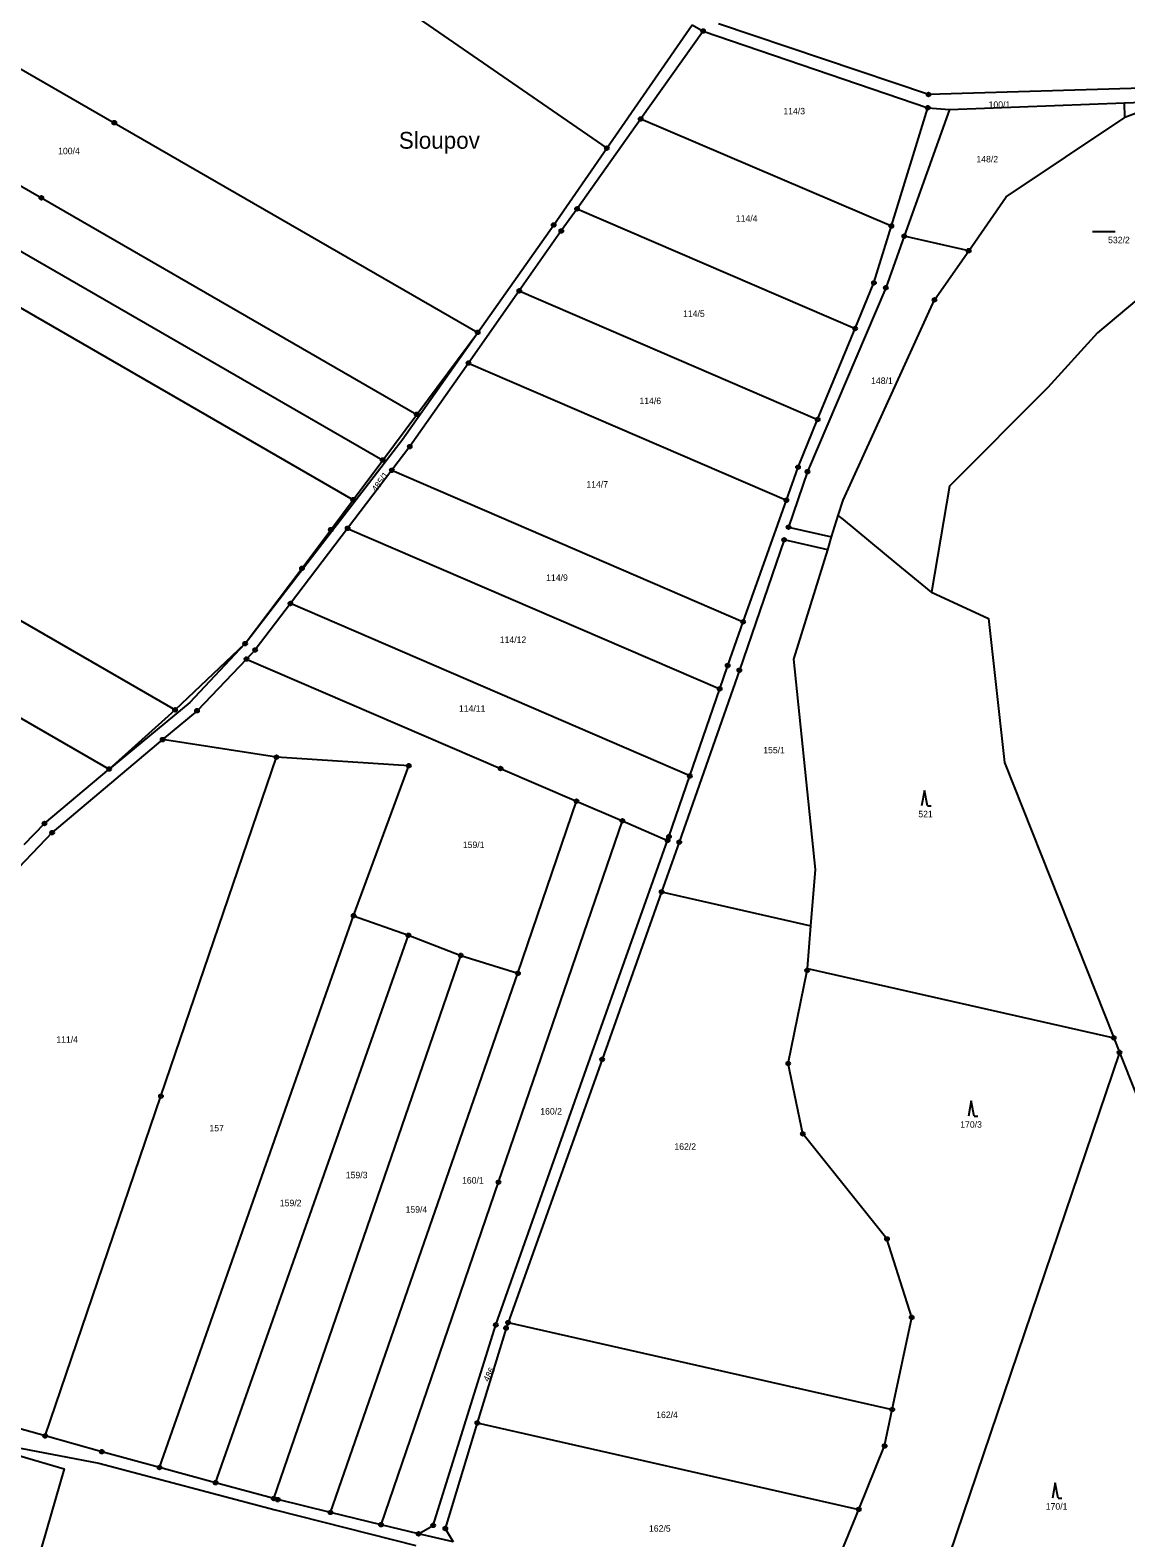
# Model space of a CAD drawing. Extents: x -758582 to -751794, y -998770 to -994350.
# Drawn here: x -756217.6 to -755930.2, y -996868.5 to -996472.9 of the extents above; entities that cross this region are included whole.
import ezdxf

# ---------------------------------------------------------------- set-up
doc = ezdxf.new("R2010")
doc.units = 0
for name, color, linetype in [('Hranice parcel', 7, 'Continuous'), ('Parcelní čísla', 7, 'Continuous'), ('Pop  PČ popisy', 7, 'Continuous'), ('Vnitřní kresba', 7, 'Continuous'), ('Značky bodu BP', 7, 'Continuous'), ('Značky kultur', 7, 'Continuous')]:
    doc.layers.add(name, color=color, linetype=linetype)

msp = doc.modelspace()

# ---------------------------------------------------------------- linework, layer by layer
at = {"layer": 'Hranice parcel'}
for p, q in [((-756066.33, -996503.89), (-756043.93, -996471.51)), ((-756043.93, -996471.51), (-756041.08, -996473.16)), ((-756041.08, -996473.16), (-756057.45, -996496.24)), ((-756041.08, -996473.16), (-755982.13, -996493.28)), ((-755976.39, -996493.79), (-755930.55, -996492.03)), ((-755930.4, -996495.89), (-755930.55, -996492.03)), ((-756057.45, -996496.24), (-756074.15, -996519.8)), ((-756057.45, -996496.24), (-755991.67, -996524.32)), ((-755991.67, -996524.32), (-755982.13, -996493.28)), ((-755976.39, -996493.79), (-755988.3, -996526.99)), ((-755982.13, -996493.28), (-755976.39, -996493.79)), ((-756074.15, -996519.8), (-756001.19, -996551.22)), ((-755971.4, -996530.81), (-755988.3, -996526.99)), ((-756089.3, -996541.32), (-756102.63, -996560.29)), ((-756089.3, -996541.32), (-756011.02, -996575.11)), ((-756011.02, -996575.11), (-756001.19, -996551.22)), ((-756116.22, -996573.74), (-756100.21, -996552.23)), ((-756102.63, -996560.29), (-756019.24, -996596.29)), ((-756125.14, -996585.72), (-756116.22, -996573.74)), ((-756132.9, -996596.13), (-756125.14, -996585.72)), ((-756122.74, -996588.41), (-756134.34, -996603.65)), ((-756122.74, -996588.41), (-756030.56, -996628.2)), ((-756030.56, -996628.2), (-756019.24, -996596.29)), ((-756007.36, -996605.92), (-756005.61, -996600.26)), ((-756134.34, -996603.65), (-756149.36, -996623.39)), ((-756134.34, -996603.65), (-756036.73, -996645.78)), ((-756008.39, -996609.26), (-756007.36, -996605.92)), ((-756044.57, -996668.63), (-756149.36, -996623.39)), ((-756044.57, -996668.63), (-756036.73, -996645.78)), ((-756196.89, -996666.8), (-756179.61, -996651.27)), ((-756153, -996663.68), (-756182.87, -996659.09)), ((-756089.66, -996720.4), (-756074.29, -996675.23)), ((-756074.29, -996675.23), (-756062.26, -996680.41)), ((-756062.26, -996680.41), (-756050.38, -996685.53)), ((-756051.97, -996699.06), (-756012.79, -996707.93)), ((-756183.71, -996850.06), (-756132.77, -996705.3)), ((-756132.77, -996705.3), (-756118.4, -996710.43)), ((-756013.73, -996719.12), (-756012.79, -996707.93)), ((-756168.97, -996854.06), (-756118.4, -996710.43)), ((-756118.4, -996710.43), (-756104.62, -996715.71)), ((-756153.73, -996858.21), (-756104.62, -996715.71)), ((-756104.62, -996715.71), (-756089.66, -996720.4)), ((-756138.83, -996861.86), (-756089.66, -996720.4)), ((-756013.73, -996719.12), (-755933.35, -996737.32)), ((-755933.35, -996737.32), (-755931.83, -996741.15)), ((-756092.26, -996812.05), (-755991.44, -996834.87)), ((-756213.7, -996841.79), (-756229.38, -996837.41)), ((-756100.32, -996838.38), (-756000.21, -996861.05)), ((-756168.97, -996854.06), (-756183.71, -996850.06)), ((-756153.73, -996858.21), (-756168.97, -996854.06)), ((-756125.58, -996865.08), (-756138.83, -996861.86)), ((-756115.72, -996867.47), (-756125.58, -996865.08)), ((-756106.65, -996869.59), (-756115.72, -996867.47))]:
    msp.add_line(p, q, dxfattribs=at)
for points in [[(-756223.89, -996395.2), (-756148.16, -996447.44), (-756066.33, -996503.89)], [(-756289.97, -996442.74), (-756195.56, -996497.21), (-756100.21, -996552.23)], [(-756311.7, -996460.95), (-756214.69, -996516.92), (-756116.22, -996573.74)], [(-756323.8, -996471.09), (-756224.19, -996528.57), (-756125.14, -996585.72)], [(-755738.63, -996514.47), (-755788.99, -996494.25), (-755817.97, -996485.34), (-755849.85, -996483.58), (-755913.99, -996487.85), (-755981.92, -996489.8), (-756037.02, -996471.24)], [(-756334.9, -996479.57), (-756234.43, -996537.55), (-756132.9, -996596.13)], [(-755930.55, -996492.03), (-755916.39, -996491.48), (-755851.5, -996487.03), (-755818.69, -996488.48), (-755807.65, -996491.97)], [(-755808.28, -996494.77), (-755818.67, -996491.26), (-755850.72, -996490.71), (-755890.14, -996491.25), (-755898.35, -996497.16), (-755911.43, -996492.83), (-755924.16, -996493.48), (-755930.4, -996495.89)], [(-755971.4, -996530.81), (-755961.54, -996516.68), (-755930.4, -996495.89)], [(-756100.21, -996552.23), (-756080.28, -996524.04), (-756066.33, -996503.89)], [(-756074.15, -996519.8), (-756078.28, -996525.63), (-756089.3, -996541.32)], [(-755815.82, -996528.07), (-755858.93, -996519.76), (-755919.17, -996536.86), (-755937.62, -996552.31), (-755950.67, -996566.72), (-755976.44, -996592.58), (-755981.16, -996620.43)], [(-755988.3, -996526.99), (-755993.15, -996540.51), (-756013.69, -996588.78), (-756018.69, -996603.35), (-756007.36, -996605.92)], [(-756001.19, -996551.22), (-755996.26, -996539.24), (-755991.67, -996524.32)], [(-756389.84, -996529.96), (-756284.41, -996590.79), (-756179.61, -996651.27)], [(-756005.61, -996600.26), (-756004.36, -996596.24), (-755980.38, -996543.69), (-755971.4, -996530.81)], [(-756403, -996547.87), (-756300.36, -996607.1), (-756196.89, -996666.8)], [(-756102.63, -996560.29), (-756118.02, -996582.2), (-756122.74, -996588.41)], [(-756019.24, -996596.29), (-756016.16, -996587.62), (-756011.02, -996575.11)], [(-756179.61, -996651.27), (-756161.24, -996633.9), (-756146.32, -996614.15), (-756138.76, -996604), (-756132.9, -996596.13)], [(-755981.16, -996620.43), (-755990.41, -996612.79), (-756004.25, -996601.37), (-756005.61, -996600.26)], [(-756008.39, -996609.26), (-756019.82, -996606.66), (-756031.57, -996640.89), (-756047.33, -996685.99), (-756051.97, -996699.06)], [(-756012.79, -996707.93), (-756011.56, -996693.13), (-756017.3, -996638.02), (-756008.39, -996609.26)], [(-755981.16, -996620.43), (-755966.24, -996627.28), (-755962.03, -996665.05), (-755933.35, -996737.32)], [(-756149.36, -996623.39), (-756158.6, -996635.55), (-756160.88, -996637.94)], [(-756036.73, -996645.78), (-756034.63, -996639.67), (-756030.56, -996628.2)], [(-756160.88, -996637.94), (-756173.86, -996651.51), (-756182.87, -996659.09)], [(-756160.88, -996637.94), (-756094.21, -996666.65), (-756074.29, -996675.23)], [(-756182.87, -996659.09), (-756211.86, -996683.49), (-756234.83, -996707.54), (-756253.45, -996735.72), (-756269.43, -996768.85), (-756277.38, -996793.04)], [(-756213.7, -996841.79), (-756183.32, -996752.66), (-756153, -996663.68)], [(-756132.77, -996705.3), (-756118.27, -996665.94), (-756153, -996663.68)], [(-756219.23, -996686.58), (-756213.87, -996681.09), (-756196.89, -996666.8)], [(-756050.38, -996685.53), (-756050.04, -996684.56), (-756044.57, -996668.63)], [(-756125.58, -996865.08), (-756094.76, -996775.21), (-756062.26, -996680.41)], [(-756115.72, -996867.47), (-756111.89, -996865.26), (-756095.44, -996812.67), (-756070.18, -996741.19), (-756050.38, -996685.53)], [(-756051.97, -996699.06), (-756067.56, -996742.99), (-756092.26, -996812.05)], [(-755991.44, -996834.87), (-755986.35, -996810.68), (-755992.83, -996790.11), (-756014.92, -996762.53), (-756018.74, -996744.05), (-756013.77, -996719.63), (-756013.73, -996719.12)], [(-755931.83, -996741.15), (-755985.33, -996899.18), (-756004.65, -996895), (-756005.17, -996894.89)], [(-755931.83, -996741.15), (-755910.72, -996794.08), (-755898.01, -996825.36)], [(-756092.26, -996812.05), (-756092.78, -996813.49), (-756100.32, -996838.38)], [(-756000.21, -996861.05), (-755993.45, -996844.42), (-755991.44, -996834.87)], [(-756100.32, -996838.38), (-756108.71, -996866.09), (-756106.65, -996869.59)], [(-756240.4, -996841.13), (-756208.7, -996850.39), (-756227.33, -996914.64), (-756266.64, -996902.35), (-756265.2, -996898.6), (-756260.73, -996899.5), (-756245.41, -996846.34)], [(-756240.4, -996841.13), (-756199.58, -996848.95), (-756153.32, -996861.2), (-756116.46, -996870.52)], [(-756183.71, -996850.06), (-756198.84, -996845.94), (-756213.7, -996841.79)], [(-756138.83, -996861.86), (-756152.69, -996858.49), (-756153.73, -996858.21)], [(-756007.03, -996890.97), (-756005.62, -996874.34), (-756000.21, -996861.05)]]:
    msp.add_lwpolyline(points, dxfattribs=at)
at = {"layer": 'Vnitřní kresba'}
for p, q in [((-756120.07, -996580.47), (-756100.21, -996552.23)), ((-756161.24, -996633.9), (-756120.07, -996580.47)), ((-756175.7, -996649.36), (-756161.24, -996633.9)), ((-756175.7, -996649.36), (-756196.89, -996666.8))]:
    msp.add_line(p, q, dxfattribs=at)
at = {"layer": 'Značky bodu BP'}
for centre, radius in [((-756041.08, -996473.16), 0.5), ((-756041.08, -996473.16), 0.0303), ((-755981.92, -996489.8), 0.5), ((-755981.92, -996489.8), 0.0303), ((-756057.45, -996496.24), 0.5), ((-756057.45, -996496.24), 0.0303), ((-755982.13, -996493.28), 0.5), ((-755982.13, -996493.28), 0.0303), ((-756195.56, -996497.21), 0.5), ((-756195.56, -996497.21), 0.0303), ((-756066.33, -996503.89), 0.5), ((-756066.33, -996503.89), 0.0303), ((-756214.69, -996516.92), 0.5), ((-756214.69, -996516.92), 0.0303), ((-756074.15, -996519.8), 0.5), ((-756074.15, -996519.8), 0.0303), ((-756080.28, -996524.04), 0.5), ((-755991.67, -996524.32), 0.5), ((-756080.28, -996524.04), 0.0303), ((-756078.28, -996525.63), 0.5), ((-756078.28, -996525.63), 0.0303), ((-755991.67, -996524.32), 0.0303), ((-755988.3, -996526.99), 0.5), ((-755988.3, -996526.99), 0.0303), ((-755971.4, -996530.81), 0.5), ((-755971.4, -996530.81), 0.0303), ((-755996.26, -996539.24), 0.5), ((-755996.26, -996539.24), 0.0303), ((-756089.3, -996541.32), 0.5), ((-756089.3, -996541.32), 0.0303), ((-755993.15, -996540.51), 0.5), ((-755993.15, -996540.51), 0.0303), ((-755980.38, -996543.69), 0.5), ((-755980.38, -996543.69), 0.0303), ((-756001.19, -996551.22), 0.5), ((-756001.19, -996551.22), 0.0303), ((-756100.21, -996552.23), 0.5), ((-756100.21, -996552.23), 0.0303), ((-756102.63, -996560.29), 0.5), ((-756102.63, -996560.29), 0.0303), ((-756116.22, -996573.74), 0.5), ((-756116.22, -996573.74), 0.0303), ((-756011.02, -996575.11), 0.5), ((-756011.02, -996575.11), 0.0303), ((-756118.02, -996582.2), 0.5), ((-756118.02, -996582.2), 0.0303), ((-756125.14, -996585.72), 0.5), ((-756125.14, -996585.72), 0.0303), ((-756016.16, -996587.62), 0.5), ((-756122.74, -996588.41), 0.5), ((-756122.74, -996588.41), 0.0303), ((-756016.16, -996587.62), 0.0303), ((-756013.69, -996588.78), 0.5), ((-756013.69, -996588.78), 0.0303), ((-756132.9, -996596.13), 0.5), ((-756132.9, -996596.13), 0.0303), ((-756019.24, -996596.29), 0.5), ((-756019.24, -996596.29), 0.0303), ((-756018.69, -996603.35), 0.5), ((-756138.76, -996604), 0.5), ((-756138.76, -996604), 0.0303), ((-756134.34, -996603.65), 0.5), ((-756134.34, -996603.65), 0.0303), ((-756019.82, -996606.66), 0.5), ((-756019.82, -996606.66), 0.0303), ((-756018.69, -996603.35), 0.0303), ((-756146.32, -996614.15), 0.5), ((-756146.32, -996614.15), 0.0303), ((-756149.36, -996623.39), 0.5), ((-756149.36, -996623.39), 0.0303), ((-756030.56, -996628.2), 0.5), ((-756030.56, -996628.2), 0.0303), ((-756161.24, -996633.9), 0.5), ((-756161.24, -996633.9), 0.0303), ((-756160.88, -996637.94), 0.5), ((-756160.88, -996637.94), 0.0303), ((-756158.6, -996635.55), 0.5), ((-756158.6, -996635.55), 0.0303), ((-756034.63, -996639.67), 0.5), ((-756034.63, -996639.67), 0.0303), ((-756031.57, -996640.89), 0.5), ((-756031.57, -996640.89), 0.0303), ((-756036.73, -996645.78), 0.5), ((-756036.73, -996645.78), 0.0303), ((-756179.61, -996651.27), 0.5), ((-756179.61, -996651.27), 0.0303), ((-756173.86, -996651.51), 0.5), ((-756173.86, -996651.51), 0.0303), ((-756182.87, -996659.09), 0.5), ((-756182.87, -996659.09), 0.0303), ((-756196.89, -996666.8), 0.5), ((-756153, -996663.68), 0.5), ((-756153, -996663.68), 0.0303), ((-756118.27, -996665.94), 0.5), ((-756118.27, -996665.94), 0.0303), ((-756094.21, -996666.65), 0.5), ((-756196.89, -996666.8), 0.0303), ((-756094.21, -996666.65), 0.0303), ((-756044.57, -996668.63), 0.5), ((-756044.57, -996668.63), 0.0303), ((-756074.29, -996675.23), 0.5), ((-756074.29, -996675.23), 0.0303), ((-756213.87, -996681.09), 0.5), ((-756213.87, -996681.09), 0.0303), ((-756062.26, -996680.41), 0.5), ((-756062.26, -996680.41), 0.0303), ((-756211.86, -996683.49), 0.5), ((-756211.86, -996683.49), 0.0303), ((-756050.38, -996685.53), 0.5), ((-756050.04, -996684.56), 0.5), ((-756050.38, -996685.53), 0.0303), ((-756050.04, -996684.56), 0.0303), ((-756047.33, -996685.99), 0.5), ((-756047.33, -996685.99), 0.0303), ((-756051.97, -996699.06), 0.5), ((-756051.97, -996699.06), 0.0303), ((-756132.77, -996705.3), 0.5), ((-756132.77, -996705.3), 0.0303), ((-756118.4, -996710.43), 0.5), ((-756118.4, -996710.43), 0.0303), ((-756104.62, -996715.71), 0.5), ((-756104.62, -996715.71), 0.0303), ((-756089.66, -996720.4), 0.5), ((-756089.66, -996720.4), 0.0303), ((-756013.77, -996719.63), 0.5), ((-756013.77, -996719.63), 0.0303), ((-755933.35, -996737.32), 0.5), ((-755933.35, -996737.32), 0.0303), ((-755931.83, -996741.15), 0.5), ((-755931.83, -996741.15), 0.0303), ((-756067.56, -996742.99), 0.5), ((-756067.56, -996742.99), 0.0303), ((-756018.74, -996744.05), 0.5), ((-756018.74, -996744.05), 0.0303), ((-756183.32, -996752.66), 0.5), ((-756183.32, -996752.66), 0.0303), ((-756014.92, -996762.53), 0.5), ((-756014.92, -996762.53), 0.0303), ((-756094.76, -996775.21), 0.5), ((-756094.76, -996775.21), 0.0303), ((-755992.83, -996790.11), 0.5), ((-755992.83, -996790.11), 0.0303), ((-756095.44, -996812.67), 0.5), ((-756095.44, -996812.67), 0.0303), ((-756092.26, -996812.05), 0.5), ((-756092.26, -996812.05), 0.0303), ((-755986.35, -996810.68), 0.5), ((-755986.35, -996810.68), 0.0303), ((-756092.78, -996813.49), 0.5), ((-756092.78, -996813.49), 0.0303), ((-755991.44, -996834.87), 0.5), ((-755991.44, -996834.87), 0.0303), ((-756100.32, -996838.38), 0.5), ((-756100.32, -996838.38), 0.0303), ((-756213.7, -996841.79), 0.5), ((-756213.7, -996841.79), 0.0303), ((-755993.45, -996844.42), 0.5), ((-755993.45, -996844.42), 0.0303), ((-756198.84, -996845.94), 0.5), ((-756198.84, -996845.94), 0.0303), ((-756183.71, -996850.06), 0.5), ((-756183.71, -996850.06), 0.0303), ((-756168.97, -996854.06), 0.5), ((-756168.97, -996854.06), 0.0303), ((-756153.73, -996858.21), 0.5), ((-756153.73, -996858.21), 0.0303), ((-756152.69, -996858.49), 0.5), ((-756152.69, -996858.49), 0.0303), ((-756138.83, -996861.86), 0.5), ((-756138.83, -996861.86), 0.0303), ((-756000.21, -996861.05), 0.5), ((-756000.21, -996861.05), 0.0303), ((-756125.58, -996865.08), 0.5), ((-756125.58, -996865.08), 0.0303), ((-756115.72, -996867.47), 0.5), ((-756115.72, -996867.47), 0.0303), ((-756111.89, -996865.26), 0.5), ((-756111.89, -996865.26), 0.0303), ((-756108.71, -996866.09), 0.5), ((-756108.71, -996866.09), 0.0303)]:
    msp.add_circle(centre, radius, dxfattribs=at)
at = {"layer": 'Značky kultur'}
for p, q in [((-755938.93, -996525.8), (-755932.93, -996525.8)), ((-755982.99, -996672.42), (-755983.74, -996676.42)), ((-755982.24, -996676.42), (-755982.99, -996672.42)), ((-755982.24, -996676.42), (-755981.24, -996676.42)), ((-755970.73, -996753.87), (-755971.48, -996757.87)), ((-755969.98, -996757.87), (-755970.73, -996753.87)), ((-755969.98, -996757.87), (-755968.98, -996757.87)), ((-755948.68, -996854.08), (-755949.43, -996858.08)), ((-755947.93, -996858.08), (-755948.68, -996854.08)), ((-755947.93, -996858.08), (-755946.93, -996858.08))]:
    msp.add_line(p, q, dxfattribs=at)

# ---------------------------------------------------------------- texts
at = {"layer": 'Parcelní čísla'}
for s, p in [('100/1', (-755966.18, -996493.33)), ('114/3', (-756020.02, -996495.03)), ('100/4', (-756210.3, -996505.49)), ('148/2', (-755969.37, -996507.63)), ('114/4', (-756032.48, -996523.18)), ('532/2', (-755934.82, -996528.84)), ('114/5', (-756046.34, -996548.17)), ('148/1', (-755997, -996565.77)), ('114/6', (-756057.78, -996571.05)), ('114/7', (-756071.7, -996592.97)), ('114/9', (-756082.26, -996617.45)), ('114/12', (-756094.43, -996633.73)), ('114/11', (-756105.13, -996651.76)), ('155/1', (-756025.3, -996662.69)), ('521', (-755984.61, -996679.47)), ('159/1', (-756104.11, -996687.54)), ('111/4', (-756210.77, -996738.63)), ('160/2', (-756083.8, -996757.47)), ('157', (-756170.6, -996761.87)), ('170/3', (-755973.62, -996760.92)), ('162/2', (-756048.61, -996766.71)), ('159/3', (-756134.82, -996774.19)), ('160/1', (-756104.33, -996775.58)), ('159/2', (-756152.13, -996781.52)), ('159/4', (-756119.14, -996783.21)), ('162/4', (-756053.38, -996837.09)), ('170/1', (-755951.18, -996861.13)), ('162/5', (-756055.28, -996866.92))]:
    msp.add_text(s, height=1.7, dxfattribs=at).set_placement(p)
for s, rotation, p in [('485/1', 54, (-756126.8, -996594.23)), ('486', 62, (-756097.37, -996827.73))]:
    msp.add_text(s, height=1.7, rotation=rotation, dxfattribs=at).set_placement(p)
at = {"layer": 'Pop  PČ popisy'}
msp.add_text('Sloupov', height=4.4, dxfattribs=at).set_placement((-756120.91, -996504.04))

doc.saveas('drawing.dxf')
